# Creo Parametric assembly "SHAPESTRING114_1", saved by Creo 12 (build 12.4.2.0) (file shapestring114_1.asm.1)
Units: Custom; MM, KILOGRAM, SECS

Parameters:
  PTC_WM_ITERATION = "0"
  PTC_WM_VERSION = "-.0"
  PTC_WM_LIFECYCLE_STATE = "In Work"
  PTC_WM_LIFECYCLE = "MO_CADDocument"
  PTC_WM_CREATED_BY = "Maximilian Roepper (Z0017RMS: MO)"
  PTC_WM_CREATED_ON = "18-Sep-26 11:36:42 AM"
  PTC_WM_MODIFIED_BY = "Maximilian Roepper (Z0017RMS: MO)"
  PTC_WM_MODIFIED_ON = "18-Sep-26 11:36:46 AM"
  PDMLINKNUMBER = "PDM000071454918"
  PTC_WM_NUMBER = "PDM000071454918"

Other parameters: WEIGHT, WEIGHT_FACTOR, WEIGHT_ADD, MC_ERRORS, SUPPLIER

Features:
  1. coordinate system
  2. imported feature
  3. component "SHAPESTRING068_1"
  4. component "SHAPESTRING110_1"
  5. component "SHAPESTRING111_1"
  6. component "SHAPESTRING112_1"
  7. component "SHAPESTRING113_1"

Other named items: DRW_VIEW_ORG, ROUGH-GROB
